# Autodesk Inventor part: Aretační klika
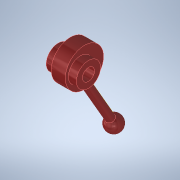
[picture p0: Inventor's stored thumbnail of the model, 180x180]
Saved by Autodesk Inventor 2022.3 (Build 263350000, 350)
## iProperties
Created: 2022-03
Part Number: Aretační klika
Material: Všeobecné
Document SubType Name: Modeling
Designer: Hra42
Density: 1 g/cm^3
Appearance: Výchozí
Sending System: SolidWorks 2012
Last Author: Hra42
Last Saved: 2025-11-13
Author: Hra42
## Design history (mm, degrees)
feature "Importovaný1"
sketch "Náčrt1"
  geometry: L1 (0, 0)-(-31.641, -18.268); L2 (-8.09, -6.98)-(-30.641, -20) reference; C1 r 3 at (0, 0) reference; 1 further point
  constraints: 2 end point, 1 parallel, 1 other
node "Těleso1"
